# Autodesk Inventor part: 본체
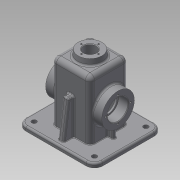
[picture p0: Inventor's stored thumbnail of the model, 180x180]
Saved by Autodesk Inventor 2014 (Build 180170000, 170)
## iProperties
Created: 2016-08
Part Number: 본체
Material: 일반
Document SubType Name: Modeling
Designer: user
Density: 1 g/cm^3
Appearance: 기본값
Author: user
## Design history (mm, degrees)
sketch "스케치1"
  geometry: L1 (-65, 57.5)-(65, 57.5); L2 (65, 57.5)-(65, -57.5); L3 (65, -57.5)-(-65, -57.5); L4 (-65, -57.5)-(-65, 57.5); L5 (-65, 57.5)-(65, -57.5); L6 (65, 57.5)-(-65, -57.5); 1 further point
  constraints: 12 end point, 2 midpoint, 2 parallel, 1 horizontal, 1 perpendicular
  dimensions: "d0" = 130 distance of L2.end L3.end; "d1" = 115 distance of L1.end L2.end
extrude "돌출1" new body sketch "스케치1" distance "d2" = 7; taper "d3" = 0 deg
sketch "스케치2"
  geometry: L1 (-32.5, 32.5)-(32.5, 32.5); L2 (32.5, 32.5)-(32.5, -32.5); L3 (32.5, -32.5)-(-32.5, -32.5); L4 (-32.5, -32.5)-(-32.5, 32.5); L5 (-32.5, 32.5)-(32.5, -32.5); L6 (32.5, 32.5)-(-32.5, -32.5); 3 further points
  constraints: 12 end point, 3 midpoint, 2 parallel, 1 coincident, 1 horizontal, 1 perpendicular
  dimensions: "d4" = 65 distance of L2.end L3.end; "d5" = 65 distance of L1.end L2.end
extrude "돌출2" join sketch "스케치2" distance "d6" = 100; taper "d7" = 0 deg
sketch "스케치3"
  geometry: L1 (60, -52.5)-(-60, -52.5); L2 (-60, -52.5)-(-60, 52.5); L3 (-60, 52.5)-(60, 52.5); L4 (60, 52.5)-(60, -52.5); L5 (60, -52.5)-(-60, 52.5); L6 (-60, -52.5)-(60, 52.5); 1 further point
  constraints: 12 end point, 2 midpoint, 2 parallel, 1 horizontal, 1 perpendicular
  dimensions: "d8" = 120 distance of L2.end L3.end; "d9" = 105 distance of L1.end L2.end
extrude "돌출3" join sketch "스케치3" distance "d10" = 3; taper "d11" = 0 deg
sketch "스케치5"
  geometry: L1 (27.5, -27.5)-(-27.5, -27.5); L2 (-27.5, -27.5)-(-27.5, 27.5); L3 (-27.5, 27.5)-(27.5, 27.5); L4 (27.5, 27.5)-(27.5, -27.5); L5 (27.5, -27.5)-(-27.5, 27.5); L6 (-27.5, -27.5)-(27.5, 27.5); 1 further point
  constraints: 12 end point, 2 midpoint, 2 parallel, 1 horizontal, 1 perpendicular
  dimensions: "d13" = 55 distance of L2.end L3.end; "d14" = 55 distance of L1.end L2.end
extrude "돌출4" cut sketch "스케치5" distance "d15" = 105; taper "d16" = 0 deg
sketch "스케치6"
  geometry: L1 (0, 0)-(-100, 0) reference; L2 (10, 85)-(10, -20) reference; C1 r 27.5 at (-45, 32.5); 1 further point
  constraints: 1 centre point
  dimensions: "d17" = 55 diameter of C1; "d18" = 32.5 distance from line of L1 C1.centre; "d19" = 55 distance from line of C1.centre L2
extrude "돌출5" join sketch "스케치6" distance "d20" = 15; taper "d21" = 0 deg
sketch "스케치7" dims "d22" = 42
  geometry: C1 r 27.5 at (0, 0) reference; 3 further points
  constraints: 2 horizontal alignment, 1 coincident, 2 other
hole "구멍1" sketch "스케치7" at (-21, 0) diameter "d23" = 3.242; stored, may be unused: countersink angle "d27" = 90 deg, drill point angle "d29" = 118 deg; dims "d24" = 8, "d25" = 4, "d26" = 2, "d28" = 10
sketch "스케치8"
  geometry: C1 r 27.5 at (0, 0) reference; C2 r 17.5 at (0, 0); 1 further point
  constraints: 1 centre point, 1 coincident
  dimensions: "d33" = 35 diameter of C2
extrude "돌출6" cut sketch "스케치8" distance "d34" = 17; taper "d35" = 0 deg
sketch "스케치9"
  geometry: C1 r 17.5 at (0, 0) reference; C2 r 15 at (0, 0); 1 further point
  constraints: 1 centre point, 1 coincident
  dimensions: "d36" = 30 diameter of C2
extrude "돌출7" cut sketch "스케치9" stored distance "d37" = 0; taper "d38" = 0 deg
sketch "스케치10"
  geometry: L1 (-32.5, 7)-(-32.5, 107) reference; L2 (65, 7)-(-65, 7) reference; L3 (-32.5, 24.5)-(-47.5, 24.5) reference; L4 (-42.5, 7)-(-42.5, 24.5); 2 further points
  constraints: 2 end point, 2 point on line, 1 perpendicular
  dimensions: "d39" = 15 horizontal distance of L4.start point (-27.5, -3)
feature "리브1" sketch "스케치10" dims "d40" = 1, "d41" = 6, "d42" = 0, "d43" = 0, "d44" = 1, "d45" = 1
node "작업 평면1"
sketch "스케치12"
  geometry: C1 r 20 at (0, 0); 1 further point
  constraints: 1 centre point, 1 coincident
  dimensions: "d47" = 40 diameter of C1
extrude "돌출8" join sketch "스케치12" stored distance "d48" = 17; taper "d49" = 7 deg
sketch "스케치13"
  geometry: C1 r 10.5 at (0, 0); 1 further point
  constraints: 1 centre point, 1 coincident
  dimensions: "d50" = 21 diameter of C1
extrude "돌출9" cut sketch "스케치13" stored distance "d51" = 17; taper "d52" = 0 deg
sketch "스케치14" dims "d53" = 29
  geometry: 3 further points
  constraints: 2 horizontal alignment, 1 coincident, 2 other
hole "구멍2" sketch "스케치14" at (14.5, 0) diameter "d54" = 2.459; stored, may be unused: countersink angle "d58" = 90 deg, drill point angle "d60" = 118 deg; dims "d55" = 7, "d56" = 4, "d57" = 2, "d59" = 9
sketch "스케치15"
  geometry: L1 (-49.5, 7)-(-41.068, 67); L2 (-57.5, 0)-(-57.5, 7) reference; L3 (57.5, 7)-(-57.5, 7) reference; L4 (-52.5, -3)-(52.5, -3) reference; L5 (-32.5, 7)-(-32.5, 107) reference; L6 (-41.068, 67)-(-32.5, 67); 1 further point
  constraints: 4 end point, 2 point on line, 1 perpendicular
  dimensions: "d64" = 8 distance of L2.end L1.start; "d65" = 70 distance from line of L1.end L4; "d66" = 98 deg angle of L1 L3
feature "리브2" sketch "스케치15" dims "d67" = 1, "d68" = 10, "d69" = 0, "d70" = 0, "d71" = 1, "d72" = 1
fillet "모깎기1" dims "d73" = 14
fillet "모깎기2" dims "d74" = 9
sketch "스케치17"
  geometry: L1 (-51, -52.5)-(51, -52.5) reference; L2 (-60, 43.5)-(-60, -43.5) reference; 2 further points
  dimensions: "d75" = 9 distance from line of L1 point (-51, -43.5); "d76" = 9 distance from line of L2 point (-51, -43.5)
hole "구멍3" sketch "스케치17" at (-51, -43.5) diameter "d77" = 8; stored, may be unused: countersink angle "d81" = 90 deg, drill point angle "d83" = 118 deg; dims "d78" = 7, "d79" = 4, "d80" = 2, "d82" = 9
sketch "스케치18"
  geometry: L1 (0, 65)-(0, 0) reference; L2 (-100, 65)-(0, 65) reference; L3 (10, 52.5)-(10, 12.5) reference; 3 further points
  constraints: 1 midpoint, 1 other
  dimensions: "d91" = 26 distance from line of L3 point (-16, 32.5); "d92" = 32.5 distance from line of L2 point (-16, 32.5)
feature "엠보싱1" sketch "스케치18" dims "d93" = 0.5, "d94" = 0
fillet "모깎기3" dims "d95" = 8
fillet "모깎기4" dims "d96" = 8
fillet "모깎기5" dims "d97" = 0.3
chamfer "모따기1" distance "d98" = 1; stored, may be unused: second distance "d99" = 2, angle "d100" = 45 deg
chamfer "모따기2" distance "d101" = 1; stored, may be unused: second distance "d102" = 2, angle "d103" = 45 deg
fillet "모깎기6" dims "d104" = 3
fillet "모깎기7" dims "d105" = 3
fillet "모깎기8" dims "d106" = 3
fillet "모깎기9" dims "d107" = 3
fillet "모깎기10" dims "d108" = 3
fillet "모깎기11" dims "d109" = 3
fillet "모깎기12" dims "d110" = 3
fillet "모깎기13" dims "d111" = 1
fillet "모깎기14" dims "d112" = 3
fillet "모깎기15" dims "d113" = 3
fillet "모깎기16" dims "d114" = 3
node "솔리드1"
pattern_circular "원형 패턴1" dims angle "d31" = 360 deg
pattern_circular "원형 패턴2" dims angle "d62" = 360 deg
mirror "대칭1"
mirror "대칭2"
pattern_linear "직사각형 패턴1" dims "d86" = 87, "d89" = 102
other parameters: "d46" = 117
